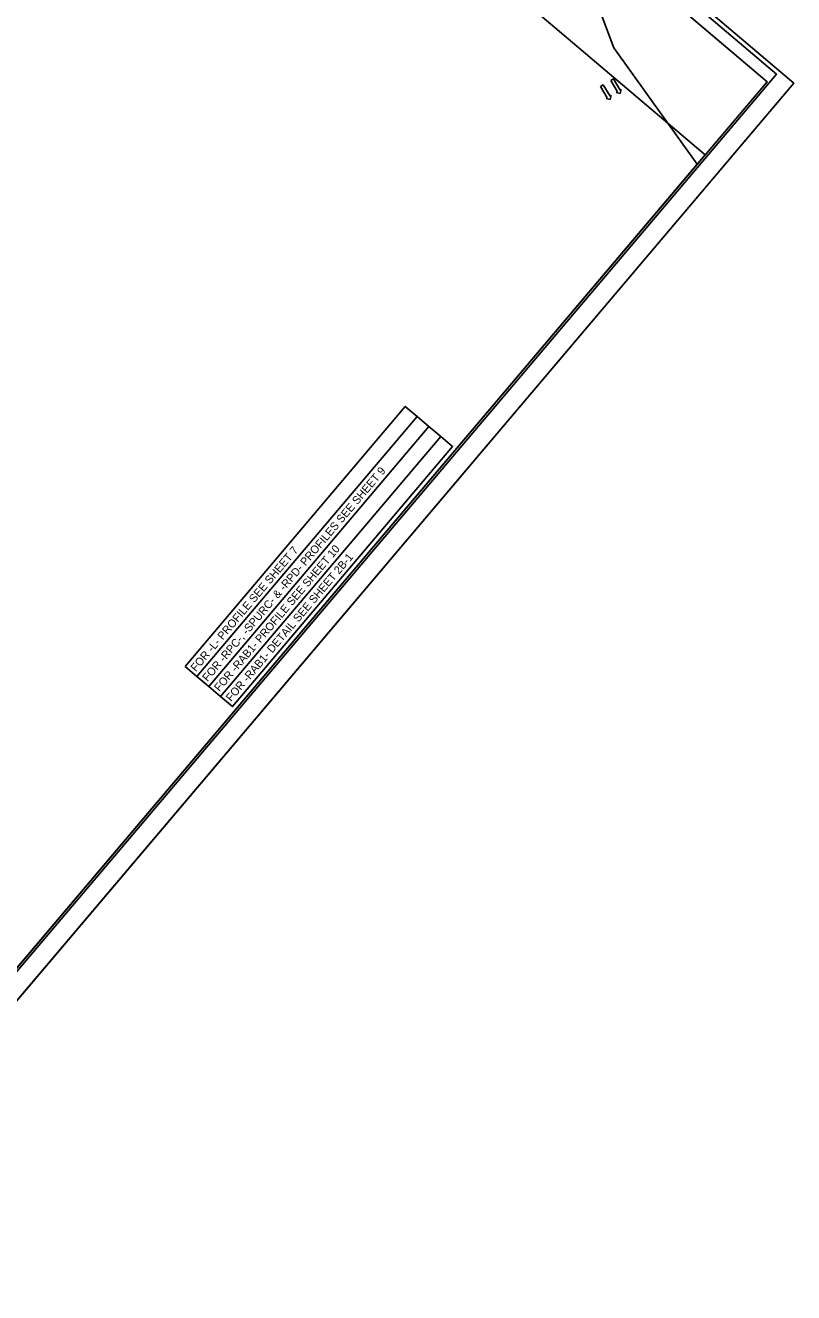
# Model space of a CAD drawing. Extents: x 1761000 to 1762924, y 421789 to 423893.
# Drawn here: x 1762108 to 1762924, y 421789 to 423135 of the extents above; entities that cross this region are included whole.
import ezdxf

# ---------------------------------------------------------------- set-up
doc = ezdxf.new("R2010")
doc.units = 0
for name, color, linetype in [('CTL Primary Horizontal and Vertical Cogo Elevation', 7, 'Continuous'), ('CTL Primary Horizontal and Vertical Cogo Number', 7, 'Continuous'), ('CTL Sheet Datum Description CELL', 7, 'Continuous'), ('Exist Roads Change in Surface', 7, 'Continuous'), ('Exist Roads Change in Surface Text', 7, 'Continuous'), ('Exist Roads EOP Other', 7, 'Continuous'), ('Exist Roads EOP Other Text', 7, 'Continuous'), ('Exist Roads Soil', 7, 'Continuous'), ('Exist Structure Major Deck Tunnel Box Culvert', 7, 'Continuous'), ('Exist Utilities Other Pole Text', 7, 'Continuous')]:
    doc.layers.add(name, color=color, linetype=linetype)

msp = doc.modelspace()

# ---------------------------------------------------------------- linework, layer by layer
at = {"layer": 'CTL Primary Horizontal and Vertical Cogo Number'}
msp.add_lwpolyline([(1761925, 421929.5), (1762829.9, 422997.7), (1762190.1, 423539.7), (1762067.8, 423395.3), (1761906.4, 423532), (1761123.8, 422608.2)], close=True, dxfattribs=at)
at = {"layer": 'CTL Sheet Datum Description CELL'}
msp.add_lwpolyline([(1761931.8, 421937.6), (1762821.5, 422987.8), (1762733.1, 423111.6), (1762720.6, 423144.4), (1762696.3, 423213.4), (1762251.7, 423590), (1762137.8, 423455.5), (1761965.3, 423601.6), (1761130.7, 422616.3)], close=True, dxfattribs=at)
at = {"layer": 'Exist Roads Change in Surface'}
msp.add_lwpolyline([(1761835.8, 421789.4), (1762924, 423073.9), (1762088.5, 423781.7), (1761000.3, 422497.2)], close=True, dxfattribs=at)
at = {"layer": 'Exist Roads Change in Surface Text'}
msp.add_line((1761835.8, 421789.4), (1762924, 423073.9), dxfattribs=at)
at = {"layer": 'Exist Roads EOP Other'}
for points in [[(1762094.7, 423754.2), (1761125.1, 422609.7), (1761926.2, 421931), (1762895.8, 423075.5)], [(1761926.2, 421931), (1761125.1, 422609.6), (1761965.3, 423601.6), (1762079.8, 423504.6), (1762209.1, 423657.2), (1762895.8, 423075.5)]]:
    msp.add_lwpolyline(points, close=True, dxfattribs=at)
at = {"layer": 'Exist Roads EOP Other Text'}
for points in [[(1762277.4, 422454.5), (1762511.3, 422730.6), (1762523.9, 422720), (1762290, 422443.8)], [(1762290, 422443.8), (1762523.9, 422720), (1762536.5, 422709.3), (1762302.5, 422433.2)], [(1762302.5, 422433.2), (1762536.5, 422709.3), (1762549.1, 422698.7), (1762315.1, 422422.5)], [(1762315.1, 422422.5), (1762549.1, 422698.7), (1762561.7, 422688), (1762327.7, 422411.8)]]:
    msp.add_lwpolyline(points, close=True, dxfattribs=at)
at = {"layer": 'Exist Roads Soil'}
msp.add_lwpolyline([(1761828.9, 421812.2), (1762905.8, 423083.4), (1762100.8, 423765.4), (1761023.9, 422494.2)], close=True, dxfattribs=at)
at = {"layer": 'Exist Structure Major Deck Tunnel Box Culvert'}
msp.add_lwpolyline([(1761125.1, 422609.6), (1761926.2, 421931), (1762895.8, 423075.5), (1762256, 423617.5), (1762101.4, 423434.9), (1761940, 423571.6)], close=True, dxfattribs=at)
at = {"layer": 'Exist Utilities Other Pole Text'}
for p, q in [((1762718.9, 423070.4), (1762721.7, 423072.1)), ((1762726, 423058.4), (1762718.9, 423070.4)), ((1762721.7, 423072.1), (1762728.9, 423060.1)), ((1762729.6, 423076.8), (1762732.4, 423078.5)), ((1762736.7, 423064.8), (1762729.6, 423076.8)), ((1762732.4, 423078.5), (1762739.5, 423066.5)), ((1762724.7, 423057.6), (1762726, 423058.4)), ((1762729.1, 423056.6), (1762724.7, 423057.6)), ((1762728.9, 423060.1), (1762730.2, 423060.9)), ((1762730.2, 423060.9), (1762729.1, 423056.6)), ((1762735.4, 423064), (1762736.7, 423064.8)), ((1762739.8, 423063), (1762735.4, 423064)), ((1762739.5, 423066.5), (1762740.8, 423067.2)), ((1762740.8, 423067.2), (1762739.8, 423063))]:
    msp.add_line(p, q, dxfattribs=at)

# ---------------------------------------------------------------- texts
at = {"layer": 'CTL Primary Horizontal and Vertical Cogo Elevation'}
for s, p in [('FOR -RPC-, -SPURC- & -RPD- PROFILES SEE SHEET 9', (1762301.3, 422437.8)), ('FOR -L- PROFILE SEE SHEET 7', (1762288.9, 422448.3)), ('FOR -RAB1- PROFILE SEE SHEET 10', (1762313.9, 422427.2)), ('FOR -RAB1- DETAIL SEE SHEET 2B-1', (1762326.4, 422416.5))]:
    msp.add_text(s, height=8.5, rotation=49.7301, dxfattribs=at).set_placement(p)

doc.saveas('drawing.dxf')
